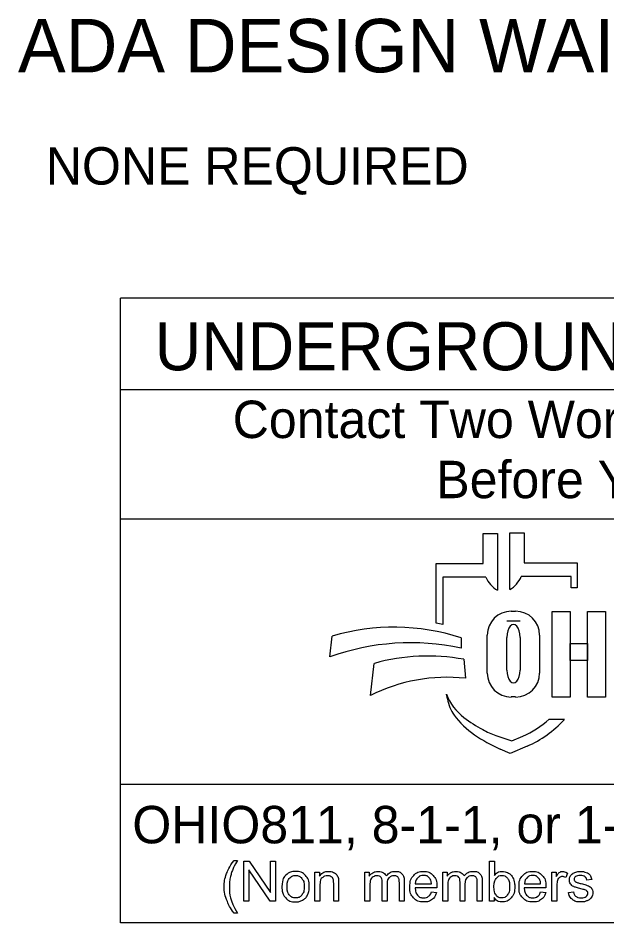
# Model space of a CAD drawing. Extents: x -7.9 to 76.1, y 0 to 22.
# Drawn here: x 1.995 to 4.196, y 2.143 to 5.529 of the extents above; entities that cross this region are included whole.
import ezdxf

# ---------------------------------------------------------------- set-up
doc = ezdxf.new("R2010")
doc.units = 0
doc.layers.add('SH_Data', color=7, linetype='Continuous')
doc.layers.add('SH_Text', color=7, linetype='Continuous')

msp = doc.modelspace()

# ---------------------------------------------------------------- linework, layer by layer
at = {"layer": 'SH_Data'}
for p, q in [((2.3775, 2.1428), (2.3775, 4.4803)), ((6.6275, 4.4803), (2.3775, 4.4803)), ((2.3775, 4.1387), (6.6275, 4.1387)), ((2.3775, 3.6553), (6.6275, 3.6553)), ((6.6275, 2.6607), (2.3775, 2.6607)), ((6.6275, 2.1428), (2.3775, 2.1428))]:
    msp.add_line(p, q, dxfattribs=at)
at = {"layer": 'SH_Text'}
for p, q in [((3.7335, 3.4883), (3.7335, 3.5998)), ((3.7335, 3.5998), (3.7872, 3.5998)), ((3.7872, 3.5998), (3.7872, 3.3877)), ((3.8329, 3.39), (3.8329, 3.6021)), ((3.8329, 3.6021), (3.8865, 3.6021)), ((3.8865, 3.6021), (3.8865, 3.4906)), ((3.5576, 3.2644), (3.5576, 3.4883)), ((3.5576, 3.4883), (3.7335, 3.4883)), ((3.8865, 3.4906), (4.0857, 3.4906)), ((4.0857, 3.4906), (4.0857, 3.3968)), ((3.5828, 3.4369), (3.5828, 3.26)), ((3.7439, 3.4369), (3.5828, 3.4369)), ((4.0625, 3.4392), (3.8761, 3.4392)), ((4.0625, 3.3968), (4.0625, 3.4392)), ((4.0857, 3.3968), (4.0625, 3.3968)), ((3.8385, 3.3091), (3.8551, 3.3091)), ((3.8718, 3.2721), (3.822, 3.2721)), ((3.7491, 3.0776), (3.7491, 3.2196)), ((3.9445, 3.2196), (3.9445, 3.0776)), ((3.1602, 3.1381), (3.1696, 3.2162)), ((3.6509, 3.2097), (3.6509, 3.1709)), ((3.822, 3.089), (3.822, 3.2114)), ((3.8718, 3.2114), (3.8718, 3.089)), ((3.6608, 3.1291), (3.6671, 3.0582)), ((3.312, 2.9936), (3.3267, 3.1137)), ((3.5997, 2.9807), (3.5967, 2.9986)), ((3.8551, 2.9882), (3.8385, 2.9882)), ((3.98, 2.9048), (4.0375, 2.9048)), ((3.7816, 2.8444), (3.841, 2.8239)), ((3.841, 2.8239), (3.8821, 2.8417)), ((3.835, 2.7769), (3.7976, 2.7934)), ((3.8983, 2.8044), (3.835, 2.7769))]:
    msp.add_line(p, q, dxfattribs=at)
for points in [[(3.991, 3.3081), (4.0589, 3.3081), (4.0589, 2.9881), (3.991, 2.9881)], [(4.1231, 3.3081), (4.1911, 3.3081), (4.1911, 2.9881), (4.1231, 2.9881)], [(4.0589, 3.1882), (4.1231, 3.1882), (4.1231, 3.1242), (4.0589, 3.1242)]]:
    msp.add_lwpolyline(points, close=True, dxfattribs=at)
for points in [[(2.8021, 2.3766), (2.8153, 2.3766)], [(2.8389, 2.2239), (2.8389, 2.3741), (2.8592, 2.3741), (2.9382, 2.2561), (2.9382, 2.3741), (2.9572, 2.3741), (2.9572, 2.2239), (2.9369, 2.2239), (2.8579, 2.3419), (2.8579, 2.2239), (2.8389, 2.2239)], [(3.7743, 2.2239), (3.7573, 2.2239), (3.7573, 2.3741), (3.7757, 2.3741), (3.7757, 2.3206)], [(3.1048, 2.2239), (3.1048, 2.3328), (3.1214, 2.3328), (3.1214, 2.3173)], [(3.2912, 2.2239), (3.2912, 2.3328), (3.3077, 2.3328), (3.3077, 2.3174)], [(3.5826, 2.2239), (3.5826, 2.3328), (3.5991, 2.3328), (3.5991, 2.3174)], [(3.9904, 2.2239), (3.9904, 2.3328), (4.007, 2.3328), (4.007, 2.3163)], [(4.0495, 2.3293), (4.043, 2.3122)], [(4.1394, 2.3046), (4.1213, 2.3022)], [(3.1233, 2.2833), (3.1233, 2.2239), (3.1048, 2.2239)], [(3.1932, 2.2908), (3.1932, 2.2239), (3.1748, 2.2239), (3.1748, 2.2901)], [(3.3097, 2.2803), (3.3097, 2.2239), (3.2912, 2.2239)], [(3.3743, 2.2871), (3.3743, 2.2239), (3.3559, 2.2239), (3.3559, 2.2946)], [(3.4388, 2.2986), (3.4388, 2.2239), (3.4203, 2.2239), (3.4203, 2.2924)], [(3.56, 2.2736), (3.4788, 2.2736)], [(3.4799, 2.2887), (3.5406, 2.2887)], [(3.601, 2.2803), (3.601, 2.2239), (3.5826, 2.2239)], [(3.6657, 2.2871), (3.6657, 2.2239), (3.6473, 2.2239), (3.6473, 2.2946)], [(3.7301, 2.2986), (3.7301, 2.2239), (3.7117, 2.2239), (3.7117, 2.2924)], [(3.968, 2.2736), (3.8868, 2.2736)], [(3.8879, 2.2887), (3.9486, 2.2887)], [(4.0088, 2.2809), (4.0088, 2.2239), (3.9904, 2.2239)], [(3.5404, 2.2591), (3.5595, 2.2567)], [(3.7743, 2.2375), (3.7743, 2.2239)], [(3.9484, 2.2591), (3.9675, 2.2567)], [(4.053, 2.2564), (4.0712, 2.2593)], [(2.8153, 2.1798), (2.8021, 2.1798)]]:
    msp.add_lwpolyline(points, dxfattribs=at)
for centre, radius, start, end in [((3.8353, 3.4736), 0.0985, 201.9296, 240.7469), ((3.7847, 3.476), 0.0985, 299.2531, 338.0704), ((3.8385, 3.2196), 0.0895, 90, 180), ((3.8551, 3.2196), 0.0895, 0, 90), ((3.4295, 2.4554), 0.8191, 79.2074, 81.0007), ((3.3997, 2.4302), 0.8191, 72.1402, 106.3144), ((3.4628, 2.2991), 0.8919, 77.8238, 109.8274), ((3.5267, 2.4094), 0.7322, 79.44, 105.8467), ((3.5987, 2.4262), 0.6357, 83.8248, 116.8021), ((3.8385, 3.0776), 0.0895, 180, 270), ((3.8551, 3.0776), 0.0895, 270, 0), ((3.7841, 3.0707), 0.2008, 201.0457, 232.5314), ((3.741, 3.0048), 0.1433, 189.6817, 216.0884), ((3.8747, 3.1022), 0.3088, 216.0884, 235.7167), ((3.9766, 3.3219), 0.5173, 232.5314, 241.794), ((3.7387, 3.1722), 0.3602, 293.4582, 312.0712), ((3.7387, 3.1722), 0.401, 293.4582, 317.8286), ((4.0412, 3.3465), 0.6044, 235.7167, 246.2325), ((3.8914, 3.1631), 0.3371, 241.794, 250.9821)]:
    msp.add_arc(centre, radius, start, end, dxfattribs=at)
for centre, start_param, end_param in [((3.8469, 3.2114), 4.712389, 7.853982), ((3.8469, 3.089), 1.570796, 4.712389)]:
    msp.add_ellipse(centre, major_axis=(0, 0.0484), ratio=0.514403, start_param=start_param, end_param=end_param, dxfattribs=at)
for points in [[(2.8021, 2.1798), (2.7869, 2.199), (2.7763, 2.2248), (2.7657, 2.2506), (2.7657, 2.2783), (2.7657, 2.3026), (2.7736, 2.325), (2.7829, 2.3509), (2.8021, 2.3766)], [(2.8153, 2.3766), (2.8029, 2.3553), (2.7989, 2.3462), (2.7927, 2.332), (2.7891, 2.3167), (2.7847, 2.2975), (2.7847, 2.2782), (2.7847, 2.2289), (2.8153, 2.1798)], [(2.9814, 2.2783), (2.9814, 2.3085), (2.9981, 2.3231), (3.0122, 2.3352), (3.0323, 2.3352), (3.0547, 2.3352), (3.069, 2.3205), (3.0832, 2.3058), (3.0832, 2.2799), (3.0832, 2.2589), (3.0769, 2.2469), (3.0706, 2.2348), (3.0586, 2.2282), (3.0466, 2.2215), (3.0323, 2.2215), (3.0095, 2.2215), (2.9954, 2.2362), (2.9814, 2.2508), (2.9814, 2.2783)], [(3.0003, 2.2783), (3.0003, 2.2574), (3.0094, 2.247), (3.0185, 2.2366), (3.0323, 2.2366), (3.046, 2.2366), (3.0551, 2.2471), (3.0642, 2.2575), (3.0642, 2.279), (3.0642, 2.2991), (3.0551, 2.3095), (3.0459, 2.3199), (3.0323, 2.3199), (3.0185, 2.3199), (3.0094, 2.3096), (3.0003, 2.2992), (3.0003, 2.2783)], [(3.1214, 2.3173), (3.1334, 2.3352), (3.156, 2.3352), (3.1659, 2.3352), (3.1741, 2.3316), (3.1823, 2.3281), (3.1864, 2.3224), (3.1905, 2.3166), (3.1922, 2.3087), (3.1932, 2.3036), (3.1932, 2.2908)], [(3.1748, 2.2901), (3.1748, 2.3013), (3.1726, 2.3069), (3.1705, 2.3125), (3.165, 2.3158), (3.1595, 2.3191), (3.1521, 2.3191), (3.1404, 2.3191), (3.1318, 2.3117), (3.1233, 2.3042), (3.1233, 2.2833)], [(3.3077, 2.3174), (3.3128, 2.3254), (3.3214, 2.3303), (3.3299, 2.3352), (3.3407, 2.3352), (3.3528, 2.3352), (3.3606, 2.3301), (3.3683, 2.3251), (3.3715, 2.3161), (3.3844, 2.3352), (3.4051, 2.3352), (3.4213, 2.3352), (3.43, 2.3262), (3.4388, 2.3172), (3.4388, 2.2986)], [(3.3559, 2.2946), (3.3559, 2.3069), (3.3514, 2.313), (3.3469, 2.3191), (3.3366, 2.3191), (3.3288, 2.3191), (3.3222, 2.315), (3.3156, 2.311), (3.3126, 2.3031), (3.3097, 2.2952), (3.3097, 2.2803)], [(3.4203, 2.2924), (3.4203, 2.3035), (3.4185, 2.3083), (3.4168, 2.3132), (3.412, 2.3162), (3.4073, 2.3191), (3.401, 2.3191), (3.3895, 2.3191), (3.3819, 2.3115), (3.3743, 2.3039), (3.3743, 2.2871)], [(3.5595, 2.2567), (3.555, 2.24), (3.5428, 2.2307), (3.5306, 2.2215), (3.5117, 2.2215), (3.4878, 2.2215), (3.4738, 2.2362), (3.4598, 2.2509), (3.4598, 2.2774), (3.4598, 2.3049), (3.474, 2.32), (3.4881, 2.3352), (3.5106, 2.3352), (3.5324, 2.3352), (3.5463, 2.3203), (3.5601, 2.3055), (3.5601, 2.2785), (3.5601, 2.2769), (3.56, 2.2736)], [(3.5406, 2.2887), (3.5394, 2.3025), (3.5337, 2.3094), (3.5249, 2.3201), (3.5108, 2.3201), (3.4981, 2.3201), (3.4894, 2.3115), (3.4808, 2.303), (3.4799, 2.2887)], [(3.5991, 2.3174), (3.6042, 2.3254), (3.6127, 2.3303), (3.6212, 2.3352), (3.6321, 2.3352), (3.6442, 2.3352), (3.6519, 2.3301), (3.6597, 2.3251), (3.6628, 2.3161), (3.6758, 2.3352), (3.6965, 2.3352), (3.7127, 2.3352), (3.7214, 2.3262), (3.7301, 2.3172), (3.7301, 2.2986)], [(3.6473, 2.2946), (3.6473, 2.3069), (3.6428, 2.313), (3.6383, 2.3191), (3.628, 2.3191), (3.6202, 2.3191), (3.6136, 2.315), (3.607, 2.311), (3.604, 2.3031), (3.601, 2.2952), (3.601, 2.2803)], [(3.7117, 2.2924), (3.7117, 2.3035), (3.7099, 2.3083), (3.7081, 2.3132), (3.7034, 2.3162), (3.6987, 2.3191), (3.6923, 2.3191), (3.6809, 2.3191), (3.6733, 2.3115), (3.6657, 2.3039), (3.6657, 2.2871)], [(3.7741, 2.2792), (3.7741, 2.2596), (3.7794, 2.2509), (3.7881, 2.2366), (3.8029, 2.2366), (3.815, 2.2366), (3.8238, 2.2471), (3.8326, 2.2576), (3.8326, 2.2784), (3.8326, 2.2998), (3.8241, 2.3099), (3.8157, 2.3201), (3.8038, 2.3201), (3.7917, 2.3201), (3.7829, 2.3096), (3.7741, 2.299), (3.7741, 2.2792)], [(3.7757, 2.3206), (3.7874, 2.3352), (3.8055, 2.3352), (3.8155, 2.3352), (3.8245, 2.3311), (3.8335, 2.3271), (3.8392, 2.3198), (3.845, 2.3124), (3.8483, 2.3021), (3.8516, 2.2918), (3.8516, 2.28), (3.8516, 2.252), (3.8378, 2.2368), (3.8239, 2.2215), (3.8046, 2.2215), (3.7853, 2.2215), (3.7743, 2.2375)], [(3.9675, 2.2567), (3.963, 2.24), (3.9508, 2.2307), (3.9386, 2.2215), (3.9196, 2.2215), (3.8958, 2.2215), (3.8818, 2.2362), (3.8678, 2.2509), (3.8678, 2.2774), (3.8678, 2.3049), (3.882, 2.32), (3.8961, 2.3352), (3.9186, 2.3352), (3.9404, 2.3352), (3.9543, 2.3203), (3.9681, 2.3055), (3.9681, 2.2785), (3.9681, 2.2769), (3.968, 2.2736)], [(3.9486, 2.2887), (3.9474, 2.3025), (3.9417, 2.3094), (3.9328, 2.3201), (3.9188, 2.3201), (3.9061, 2.3201), (3.8974, 2.3115), (3.8888, 2.303), (3.8879, 2.2887)], [(4.007, 2.3163), (4.0133, 2.3278), (4.0187, 2.3315), (4.0241, 2.3352), (4.0305, 2.3352), (4.0398, 2.3352), (4.0495, 2.3293)], [(4.043, 2.3122), (4.0363, 2.3162), (4.0295, 2.3162), (4.0235, 2.3162), (4.0187, 2.3125), (4.0139, 2.3089), (4.0119, 2.3024), (4.0088, 2.2926), (4.0088, 2.2809)], [(4.1213, 2.3022), (4.1201, 2.3106), (4.1142, 2.3153), (4.1083, 2.3201), (4.0975, 2.3201), (4.0848, 2.3201), (4.0794, 2.3159), (4.0739, 2.3116), (4.0739, 2.306), (4.0739, 2.3024), (4.0762, 2.2995), (4.0785, 2.2966), (4.0833, 2.2946), (4.086, 2.2936), (4.0996, 2.2899), (4.1192, 2.2847), (4.1269, 2.2813), (4.1347, 2.278), (4.1391, 2.2717), (4.1435, 2.2653), (4.1435, 2.2559), (4.1435, 2.2467), (4.1381, 2.2386), (4.1327, 2.2304), (4.1226, 2.226), (4.1124, 2.2215), (4.0996, 2.2215), (4.0784, 2.2215), (4.0672, 2.2303), (4.0561, 2.2391), (4.053, 2.2564)], [(4.0712, 2.2593), (4.0727, 2.2483), (4.0798, 2.2425), (4.0868, 2.2366), (4.0995, 2.2366), (4.1122, 2.2366), (4.1184, 2.2418), (4.1245, 2.247), (4.1245, 2.254), (4.1245, 2.2602), (4.1191, 2.2638), (4.1153, 2.2663), (4.1002, 2.2701), (4.0799, 2.2752), (4.072, 2.2789), (4.0642, 2.2827), (4.0601, 2.2893), (4.0561, 2.2959), (4.0561, 2.3038), (4.0561, 2.3111), (4.0594, 2.3173), (4.0628, 2.3235), (4.0685, 2.3276), (4.0728, 2.3308), (4.0803, 2.333), (4.0877, 2.3352), (4.0962, 2.3352), (4.109, 2.3352), (4.1187, 2.3315), (4.1284, 2.3278), (4.133, 2.3215), (4.1377, 2.3152), (4.1394, 2.3046)], [(3.4788, 2.2736), (3.4799, 2.2557), (3.489, 2.2462), (3.4981, 2.2366), (3.5117, 2.2366), (3.5219, 2.2366), (3.5291, 2.242), (3.5362, 2.2473), (3.5404, 2.2591)], [(3.8868, 2.2736), (3.8879, 2.2557), (3.897, 2.2462), (3.9061, 2.2366), (3.9197, 2.2366), (3.9299, 2.2366), (3.937, 2.242), (3.9442, 2.2473), (3.9484, 2.2591)]]:
    msp.add_open_spline(points, degree=3, dxfattribs=at)

# ---------------------------------------------------------------- texts
for s, height, p in [('ADA DESIGN WAIVERS', 0.2, (1.9944, 5.3256)), ('  NONE REQUIRED                          ', 0.14, (1.9944, 4.9056)), ('UNDERGROUND UTILITIES', 0.18, (2.5057, 4.2106)), ('Contact Two Working Days', 0.14, (2.7972, 3.9571)), ('Before You Dig', 0.14, (3.5583, 3.7321)), ('OHIO811, 8-1-1, or 1-800-362-2764', 0.14, (2.422, 2.4406))]:
    msp.add_text(s, height=height, dxfattribs=at).set_placement(p)

doc.saveas('drawing.dxf')
